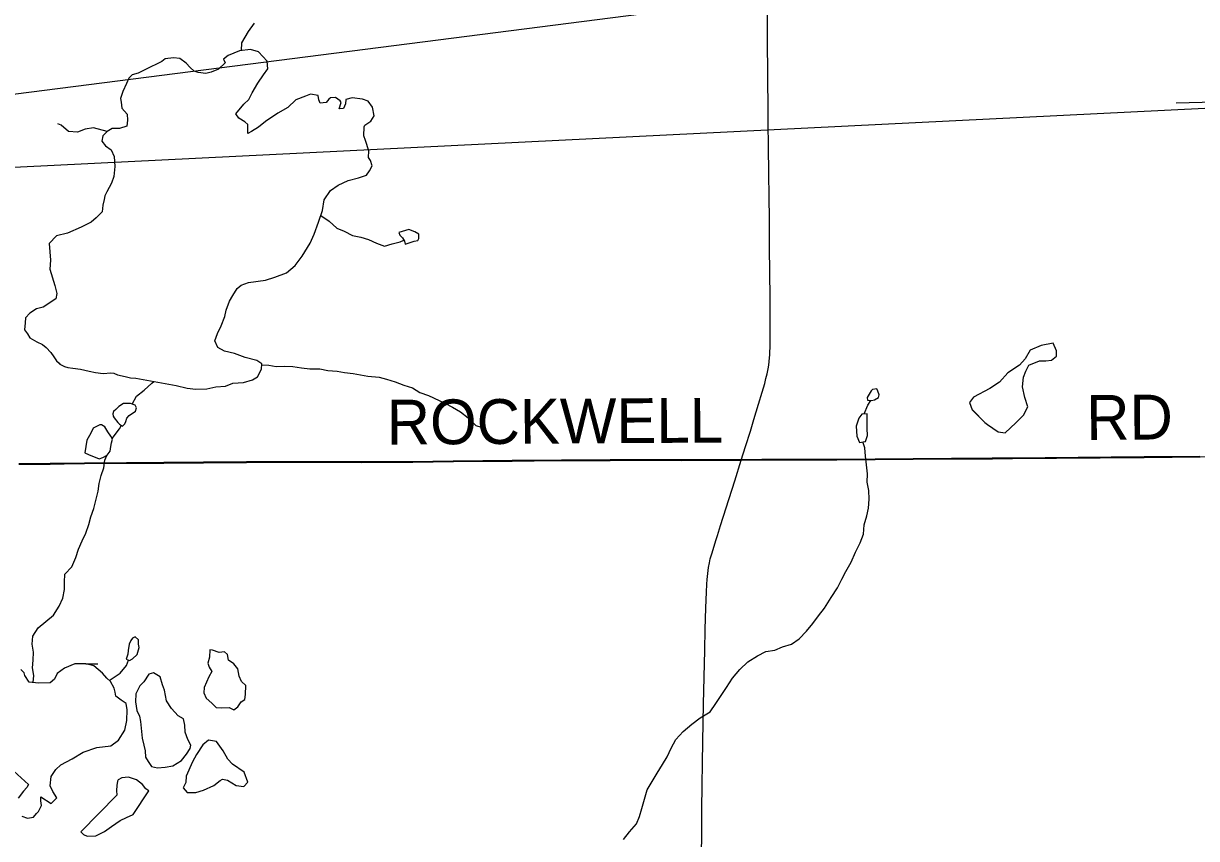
# Model space of a CAD drawing. Extents: x 0 to 34, y 0 to 22.
# Drawn here: x 6.114 to 7.601, y 17.032 to 18.065 of the extents above; entities that cross this region are included whole.
import ezdxf

# ---------------------------------------------------------------- set-up
doc = ezdxf.new("R2010")
doc.units = 0
for name, color, linetype in [('GM_X_Corporation', 7, 'Continuous'), ('GM_X_County_Road', 7, 'Continuous'), ('GM_X_County_Road_Text', 7, 'Continuous'), ('GM_X_Minor_Lake', 7, 'Continuous'), ('GM_X_Minor_River', 7, 'Continuous'), ('GM_X_Township_Road', 7, 'Continuous'), ('SH_Text', 7, 'Continuous')]:
    doc.layers.add(name, color=color, linetype=linetype)

msp = doc.modelspace()

# ---------------------------------------------------------------- linework, layer by layer
at = {"layer": 'GM_X_Corporation'}
for points in [[(7.6058, 17.5164), (7.5349, 17.5157), (7.3678, 17.5141), (7.3423, 17.514), (7.2907, 17.5138), (7.1453, 17.5127), (7.1242, 17.5126), (7.0981, 17.5126), (7.0758, 17.5124), (7.0504, 17.5124), (7.0238, 17.5123), (6.9875, 17.512), (6.9483, 17.512), (6.9334, 17.5121), (6.8907, 17.5122), (6.8578, 17.512), (6.7963, 17.5117), (6.7615, 17.5114), (6.7336, 17.5112), (6.659, 17.5104), (6.6074, 17.5097), (6.5789, 17.5096), (6.5428, 17.5095), (6.5174, 17.5095), (6.4677, 17.5096), (6.4548, 17.5095), (6.4362, 17.5096), (6.3967, 17.5095), (6.3422, 17.509), (6.3074, 17.5087), (6.2919, 17.5085), (6.2627, 17.5083), (6.2447, 17.5083), (6.1912, 17.5079), (6.1652, 17.5075), (6.1478, 17.5073), (6.108, 17.507)], [(6.108, 17.507), (6.1478, 17.5073), (6.1652, 17.5075), (6.1912, 17.5079), (6.2447, 17.5083), (6.2627, 17.5083), (6.2919, 17.5085), (6.3074, 17.5087), (6.3422, 17.509), (6.3967, 17.5095), (6.4362, 17.5096), (6.4548, 17.5095), (6.4677, 17.5096), (6.5174, 17.5095), (6.5428, 17.5095), (6.5789, 17.5096), (6.6074, 17.5097), (6.659, 17.5104), (6.7336, 17.5112), (6.7615, 17.5114), (6.7963, 17.5117), (6.8578, 17.512), (6.8907, 17.5122), (6.9334, 17.5121), (6.9483, 17.512), (6.9875, 17.512), (7.0238, 17.5123), (7.0504, 17.5124), (7.0758, 17.5124), (7.0981, 17.5126), (7.1242, 17.5126), (7.1453, 17.5127), (7.2907, 17.5138), (7.3423, 17.514), (7.3678, 17.5141), (7.5349, 17.5157), (7.6058, 17.5164)]]:
    msp.add_lwpolyline(points, dxfattribs=at)
at = {"layer": 'GM_X_County_Road'}
for points in [[(7.024, 17.5117), (7.0296, 17.5289), (7.0357, 17.5485), (7.0402, 17.5631), (7.0462, 17.5825), (7.0507, 17.5977), (7.0539, 17.6089), (7.0555, 17.615), (7.057, 17.6212), (7.0583, 17.6274), (7.059, 17.632), (7.0596, 17.6366), (7.06, 17.6413), (7.0602, 17.6451), (7.0607, 17.6584), (7.0608, 17.6656), (7.0608, 17.6743), (7.0608, 17.6897), (7.0608, 17.7179), (7.06, 17.7812), (7.0598, 17.8195), (7.0595, 17.8435), (7.059, 17.8774), (7.0587, 17.9072), (7.0586, 17.9179), (7.0584, 17.9305), (7.0582, 17.9612), (7.0579, 17.9922), (7.0574, 18.0516), (7.0572, 18.0766)], [(6.1082, 17.5065), (6.148, 17.5068), (6.1654, 17.507), (6.1914, 17.5074), (6.2449, 17.5077), (6.2629, 17.5078), (6.2921, 17.508), (6.3076, 17.5081), (6.3424, 17.5084), (6.3969, 17.5089), (6.4364, 17.509), (6.455, 17.509), (6.4679, 17.509), (6.5176, 17.509), (6.543, 17.5089), (6.5791, 17.509), (6.6077, 17.5091), (6.6592, 17.5098), (6.7338, 17.5106), (6.7617, 17.5108), (6.7965, 17.5111), (6.858, 17.5114), (6.8909, 17.5116), (6.9336, 17.5115), (6.9485, 17.5114), (6.9877, 17.5115), (7.024, 17.5117)], [(6.9738, 17.0165), (6.974, 17.0327), (6.974, 17.0507), (6.9741, 17.0618), (6.9742, 17.0699), (6.9745, 17.0984), (6.975, 17.1289), (6.976, 17.1792), (6.9764, 17.2024), (6.9779, 17.2709), (6.9784, 17.297), (6.9792, 17.3243), (6.9799, 17.3443), (6.9804, 17.3546), (6.9809, 17.3604), (6.9817, 17.3681), (6.9826, 17.3758), (6.9837, 17.3814), (6.9849, 17.3866), (6.9871, 17.3943), (6.9917, 17.4098), (6.9938, 17.4163), (6.9977, 17.4287), (7.005, 17.4511), (7.016, 17.4854), (7.024, 17.5117)], [(7.024, 17.5117), (7.0506, 17.5119), (7.076, 17.5119), (7.0983, 17.512), (7.1244, 17.512), (7.1455, 17.5122), (7.2909, 17.5132), (7.3425, 17.5134), (7.368, 17.5136), (7.5351, 17.5151), (7.606, 17.5158), (7.6644, 17.5163), (7.8224, 17.5169)]]:
    msp.add_lwpolyline(points, dxfattribs=at)
at = {"layer": 'GM_X_Minor_Lake'}
for p, q in [((6.5981, 17.7856), (6.6095, 17.7895)), ((6.2566, 17.6157), (6.3077, 17.6062)), ((7.1889, 17.5997), (7.1836, 17.5913)), ((7.317, 17.5753), (7.333, 17.5595)), ((7.333, 17.5595), (7.3178, 17.5749)), ((6.229, 17.5654), (6.2336, 17.5596)), ((7.1699, 17.5548), (7.1706, 17.5423)), ((6.1964, 17.5189), (6.2101, 17.5133)), ((6.2478, 17.2785), (6.2468, 17.2702)), ((6.3492, 17.2368), (6.3429, 17.2235)), ((6.2622, 17.1804), (6.2647, 17.1592)), ((6.1612, 17.1254), (6.1756, 17.1331)), ((6.3285, 17.1293), (6.3203, 17.1111)), ((6.253, 17.0624), (6.2728, 17.0925))]:
    msp.add_line(p, q, dxfattribs=at)
for points in [[(6.3077, 17.6062), (6.3214, 17.6029), (6.3324, 17.6015), (6.3464, 17.602), (6.3577, 17.6047), (6.3702, 17.6056), (6.3796, 17.6095), (6.3929, 17.6103), (6.4042, 17.6134), (6.4106, 17.6173), (6.4158, 17.6272), (6.4161, 17.634), (6.4097, 17.6381), (6.3953, 17.6418), (6.3816, 17.647), (6.3687, 17.6499), (6.3603, 17.6544), (6.3565, 17.6628), (6.3598, 17.6723), (6.3647, 17.6818), (6.3691, 17.6936), (6.3709, 17.7019), (6.3754, 17.7133), (6.3795, 17.7206), (6.3851, 17.7293), (6.39, 17.7335), (6.3994, 17.737), (6.421, 17.7399), (6.4327, 17.7437), (6.4474, 17.7492), (6.4583, 17.7583), (6.4673, 17.7705), (6.4774, 17.7866), (6.4826, 17.7983), (6.4882, 17.8132), (6.4933, 17.828), (6.4951, 17.8417), (6.5034, 17.8535), (6.5132, 17.8604), (6.5256, 17.8662), (6.5388, 17.8697), (6.549, 17.8732), (6.5528, 17.8785), (6.5561, 17.885), (6.5542, 17.8914), (6.5515, 17.8952), (6.5518, 17.9039), (6.5475, 17.9168), (6.5456, 17.9228), (6.5459, 17.9342), (6.547, 17.9365), (6.5545, 17.9415), (6.5586, 17.9484), (6.5567, 17.959), (6.5509, 17.9669), (6.5437, 17.9695), (6.5308, 17.9709), (6.5229, 17.9689), (6.5222, 17.9636), (6.5196, 17.9575), (6.5143, 17.9571), (6.5169, 17.9651), (6.5157, 17.9674), (6.5096, 17.9715), (6.5032, 17.9711), (6.501, 17.9692), (6.4976, 17.965), (6.49, 17.9641), (6.4885, 17.9683), (6.4877, 17.974), (6.4778, 17.9758), (6.4718, 17.9731), (6.4593, 17.9685), (6.4492, 17.9589), (6.4364, 17.9516), (6.4209, 17.9409), (6.4119, 17.934), (6.4032, 17.9282), (6.3983, 17.9259), (6.3986, 17.9373), (6.3948, 17.9407), (6.3872, 17.9452), (6.3834, 17.9508), (6.3935, 17.963), (6.3999, 17.9688), (6.404, 17.9775), (6.4111, 17.9897), (6.4182, 18), (6.4238, 18.008), (6.423, 18.0175), (6.4119, 18.0295), (6.4017, 18.0325), (6.3877, 18.0305), (6.3734, 18.0247), (6.3677, 18.0201), (6.3696, 18.0152), (6.3614, 18.0072), (6.3519, 18.0037), (6.3452, 18.0017), (6.3353, 18.0032), (6.3304, 18.005)], [(6.3304, 18.005), (6.3254, 18.0095), (6.3201, 18.0148), (6.3121, 18.0208), (6.3041, 18.0219), (6.2935, 18.0203), (6.2894, 18.0172), (6.2826, 18.0138), (6.2754, 18.0103), (6.2596, 18.0022), (6.2517, 18.0003), (6.2475, 17.996), (6.2446, 17.9892), (6.2401, 17.9789), (6.2372, 17.9702), (6.2379, 17.9656), (6.2388, 17.9581), (6.2453, 17.9505), (6.2461, 17.9426), (6.245, 17.9353), (6.2359, 17.9322), (6.2265, 17.9322), (6.2201, 17.9283), (6.2148, 17.923), (6.2133, 17.9161), (6.2179, 17.9101), (6.2252, 17.9052), (6.229, 17.8965), (6.2299, 17.884), (6.2285, 17.8711), (6.2255, 17.8628), (6.2195, 17.8517), (6.2173, 17.8468), (6.2162, 17.8422), (6.2147, 17.835), (6.2137, 17.8266), (6.2062, 17.819), (6.1998, 17.8136), (6.1873, 17.8071), (6.17, 17.7994), (6.156, 17.7962), (6.1466, 17.7863), (6.1483, 17.7651), (6.1476, 17.7537), (6.1538, 17.7333), (6.1562, 17.723), (6.1551, 17.7162), (6.1389, 17.7055), (6.1306, 17.7035), (6.1219, 17.6981), (6.1167, 17.692), (6.116, 17.6859), (6.1153, 17.6768), (6.1191, 17.6719), (6.1222, 17.6666), (6.1309, 17.6618), (6.1381, 17.6584), (6.1427, 17.6543), (6.1488, 17.6483), (6.1526, 17.6426), (6.1557, 17.6377), (6.1591, 17.6347), (6.1599, 17.6332), (6.166, 17.6306), (6.1702, 17.6291), (6.1766, 17.6284), (6.1861, 17.6269), (6.1974, 17.6247), (6.2054, 17.6229), (6.2149, 17.6215), (6.2247, 17.6223), (6.2285, 17.622), (6.2334, 17.6197), (6.2429, 17.6179), (6.2497, 17.616), (6.2566, 17.6157)], [(6.6095, 17.7895), (6.614, 17.7902), (6.6155, 17.7925), (6.6154, 17.7982), (6.6101, 17.8012), (6.6025, 17.8042), (6.5901, 17.8003), (6.5912, 17.7969), (6.5947, 17.7935), (6.597, 17.7894), (6.5981, 17.7856)], [(7.4197, 17.6599), (7.4042, 17.6571), (7.3906, 17.6513), (7.3842, 17.6402), (7.3771, 17.6319), (7.362, 17.6226), (7.3515, 17.6104), (7.3395, 17.6024), (7.3188, 17.5916), (7.3135, 17.5847), (7.317, 17.5753)], [(7.333, 17.5595), (7.3364, 17.5568), (7.3497, 17.5478), (7.3588, 17.5464), (7.3724, 17.559), (7.3821, 17.5689), (7.3874, 17.5792), (7.3839, 17.5913), (7.3807, 17.6046), (7.3818, 17.6167), (7.3851, 17.6243), (7.3888, 17.6319), (7.4024, 17.6377), (7.4104, 17.6378), (7.4175, 17.6386), (7.4239, 17.6436), (7.4239, 17.6504), (7.4197, 17.6599), (7.4042, 17.6571), (7.3906, 17.6513), (7.3842, 17.6402), (7.3771, 17.6319), (7.362, 17.6226), (7.3515, 17.6104), (7.3395, 17.6024), (7.3188, 17.5916), (7.3135, 17.5847), (7.317, 17.5753)], [(7.333, 17.5595), (7.3364, 17.5568), (7.3497, 17.5478), (7.3588, 17.5464), (7.3724, 17.559), (7.3821, 17.5689), (7.3874, 17.5792), (7.3839, 17.5913), (7.3807, 17.6046), (7.3818, 17.6167), (7.3851, 17.6243), (7.3888, 17.6319), (7.4024, 17.6377), (7.4104, 17.6378), (7.4175, 17.6386), (7.4239, 17.6436), (7.4239, 17.6504), (7.4197, 17.6599)], [(7.1836, 17.5913), (7.184, 17.5879), (7.1893, 17.5872), (7.1931, 17.588), (7.198, 17.591), (7.1988, 17.5945), (7.1972, 17.599), (7.196, 17.602), (7.1904, 17.6012), (7.1889, 17.5997)], [(6.2336, 17.5596), (6.2358, 17.5575), (6.2396, 17.5549), (6.2423, 17.5576), (6.2437, 17.5606), (6.2452, 17.5648), (6.2478, 17.5682), (6.2561, 17.5736), (6.2572, 17.5782), (6.2557, 17.5812), (6.2496, 17.5834), (6.2409, 17.5834), (6.2349, 17.5795), (6.2311, 17.5757), (6.2281, 17.5734), (6.2274, 17.5704), (6.2278, 17.5673), (6.229, 17.5654)], [(7.1706, 17.5423), (7.1739, 17.534), (7.1818, 17.5355), (7.184, 17.5428), (7.1836, 17.5519), (7.1839, 17.5606), (7.1838, 17.5705), (7.177, 17.57), (7.1732, 17.5651), (7.1699, 17.5548)], [(6.2101, 17.5133), (6.2146, 17.5149), (6.2202, 17.518), (6.224, 17.5229), (6.2247, 17.529), (6.2258, 17.5336), (6.2269, 17.5381), (6.2246, 17.5423), (6.2211, 17.5476), (6.2173, 17.554), (6.2131, 17.5566), (6.2108, 17.5566), (6.2022, 17.5524), (6.1996, 17.5459), (6.1943, 17.5371), (6.1918, 17.5208), (6.1964, 17.5189)], [(6.2468, 17.2702), (6.2464, 17.2656), (6.2442, 17.2595), (6.2484, 17.2577), (6.2522, 17.26), (6.2582, 17.2653), (6.2607, 17.2741), (6.26, 17.2782), (6.2599, 17.2839), (6.2557, 17.2877), (6.2523, 17.2858), (6.2501, 17.2831), (6.2478, 17.2785)], [(6.3429, 17.2235), (6.3426, 17.2167), (6.3456, 17.2099), (6.3529, 17.2035), (6.3582, 17.1982), (6.3647, 17.1975), (6.3749, 17.1983), (6.3806, 17.1953), (6.3859, 17.1988), (6.39, 17.2053), (6.3945, 17.2083), (6.3956, 17.2144), (6.3959, 17.2262), (6.3905, 17.2311), (6.3874, 17.2379), (6.3859, 17.247), (6.3809, 17.2534), (6.374, 17.2579), (6.3725, 17.2651), (6.369, 17.2688), (6.3622, 17.268), (6.3535, 17.2706), (6.3501, 17.271), (6.3498, 17.2619), (6.3479, 17.2543), (6.3495, 17.2493), (6.353, 17.2437), (6.3492, 17.2368)], [(6.1756, 17.1331), (6.1895, 17.1416), (6.2072, 17.1474), (6.2246, 17.1494), (6.2344, 17.1567), (6.2426, 17.1693), (6.2452, 17.1818), (6.2455, 17.1951), (6.2443, 17.203), (6.2378, 17.2075), (6.2313, 17.2124), (6.2302, 17.2177), (6.229, 17.2226), (6.2244, 17.2309), (6.2198, 17.2351), (6.2144, 17.2415), (6.2034, 17.2509), (6.1932, 17.2535), (6.1792, 17.2533), (6.166, 17.2479), (6.1565, 17.2414), (6.1532, 17.2342), (6.1479, 17.2292), (6.1332, 17.2291), (6.1214, 17.2301), (6.1157, 17.2388), (6.1149, 17.2422), (6.1107, 17.2464)], [(6.2647, 17.1592), (6.2666, 17.1505), (6.2682, 17.1433), (6.2687, 17.135), (6.2721, 17.1297), (6.2763, 17.1233), (6.2839, 17.1218), (6.2937, 17.1223), (6.3032, 17.1242), (6.3145, 17.1311), (6.3209, 17.1391), (6.3253, 17.146), (6.3261, 17.1502), (6.3226, 17.1577), (6.3191, 17.1668), (6.3187, 17.1755), (6.3171, 17.1839), (6.3102, 17.1876), (6.3018, 17.197), (6.2953, 17.2065), (6.2926, 17.2201), (6.2903, 17.2269), (6.2875, 17.2371), (6.2788, 17.242), (6.2731, 17.2404), (6.2668, 17.2305), (6.2615, 17.2255), (6.2563, 17.2153), (6.256, 17.2054), (6.2576, 17.1944), (6.2611, 17.1872), (6.2622, 17.1804)], [(6.3203, 17.1111), (6.32, 17.1031), (6.3166, 17.0963), (6.3216, 17.0902), (6.3326, 17.0903), (6.3424, 17.0931), (6.3552, 17.0992), (6.3635, 17.1057), (6.3665, 17.1073), (6.3726, 17.1058), (6.3836, 17.0991), (6.3935, 17.098), (6.3983, 17.1033), (6.3937, 17.1162), (6.3789, 17.1263), (6.3731, 17.1327), (6.367, 17.1433), (6.3586, 17.155), (6.3487, 17.1568), (6.3416, 17.1507), (6.3333, 17.1385), (6.3285, 17.1293)], [(6.1118, 17.0602), (6.119, 17.058), (6.1269, 17.0592), (6.1303, 17.0638), (6.1329, 17.0664), (6.137, 17.074), (6.1359, 17.0797), (6.1362, 17.0847), (6.1491, 17.0764), (6.1548, 17.0818), (6.1563, 17.0837), (6.1513, 17.0916), (6.1478, 17.0988), (6.1489, 17.1105), (6.1552, 17.1193), (6.1612, 17.1254)], [(6.1019, 17.1174), (6.1202, 17.1005), (6.1183, 17.0966), (6.1142, 17.0921), (6.1071, 17.0833)], [(6.2728, 17.0925), (6.269, 17.0951), (6.2648, 17.1004), (6.2575, 17.1064), (6.2473, 17.1098), (6.2386, 17.1089), (6.2341, 17.1066), (6.2333, 17.1047), (6.2322, 17.0994), (6.2319, 17.093), (6.2323, 17.0869), (6.1869, 17.0403), (6.1899, 17.0369), (6.1949, 17.035), (6.2059, 17.0355), (6.2168, 17.0409), (6.2254, 17.0474), (6.2367, 17.0547), (6.2447, 17.0586), (6.253, 17.0624)]]:
    msp.add_lwpolyline(points, dxfattribs=at)
at = {"layer": 'GM_X_Minor_River'}
for points in [[(6.3903, 18.0309), (6.391, 18.0408), (6.3992, 18.0552), (6.4071, 18.0655)], [(6.2201, 17.9283), (6.2026, 17.9331), (6.1924, 17.9312), (6.1826, 17.9277), (6.1712, 17.9283), (6.1617, 17.9362), (6.1575, 17.9381)], [(6.4912, 17.822), (6.5018, 17.8148), (6.5113, 17.8058), (6.5208, 17.8021), (6.5314, 17.7964), (6.5417, 17.7942), (6.5515, 17.7913), (6.5618, 17.7868), (6.5717, 17.7831), (6.5815, 17.7858), (6.5917, 17.7886), (6.5963, 17.7906)], [(6.4161, 17.6324), (6.4249, 17.6322), (6.4343, 17.6303), (6.4453, 17.6308), (6.4555, 17.6305), (6.4665, 17.6287), (6.4771, 17.6273), (6.4896, 17.6274), (6.4998, 17.6252), (6.5116, 17.6245), (6.5211, 17.6227), (6.532, 17.6216), (6.5506, 17.618), (6.565, 17.6169), (6.5745, 17.6144), (6.5851, 17.611), (6.5961, 17.6066), (6.6071, 17.6032), (6.6166, 17.5976), (6.6276, 17.5935), (6.6481, 17.5838), (6.658, 17.579), (6.6683, 17.573), (6.6778, 17.5655), (6.6877, 17.5557), (6.6942, 17.5534)], [(6.2517, 17.5826), (6.2571, 17.5926), (6.2669, 17.6006), (6.2767, 17.6094), (6.2792, 17.6115)], [(7.18, 17.5702), (7.1848, 17.5815), (7.1886, 17.5873)], [(6.2263, 17.5392), (6.2359, 17.5515), (6.2382, 17.5559)], [(6.9613, 17.177), (6.9722, 17.1851), (6.9846, 17.1928), (6.9918, 17.203), (6.9985, 17.2133), (7.0056, 17.2236), (7.0131, 17.2354), (7.0225, 17.2461), (7.0326, 17.2561), (7.0446, 17.2637), (7.0552, 17.2691), (7.0665, 17.2707), (7.0764, 17.275), (7.0877, 17.2785), (7.0975, 17.285), (7.1068, 17.2949), (7.1147, 17.3045), (7.1222, 17.3144), (7.1297, 17.3239), (7.1383, 17.3376), (7.1462, 17.3498), (7.1518, 17.3609), (7.1566, 17.3704), (7.1637, 17.3822), (7.1689, 17.3951), (7.1749, 17.4069), (7.1793, 17.418), (7.18, 17.4297), (7.1833, 17.4411), (7.1855, 17.451), (7.1865, 17.4624), (7.1861, 17.4734), (7.1837, 17.4836), (7.1844, 17.4942), (7.1828, 17.5056), (7.1816, 17.5166), (7.1807, 17.5272), (7.1781, 17.5348)], [(6.1264, 17.2297), (6.127, 17.2385), (6.1255, 17.2484), (6.1261, 17.2579), (6.1268, 17.2681), (6.1252, 17.2783), (6.1259, 17.2886), (6.1326, 17.2989), (6.1424, 17.3073), (6.1522, 17.3153), (6.1593, 17.3264), (6.1637, 17.3367), (6.1659, 17.3477), (6.1662, 17.3571), (6.1665, 17.367), (6.1752, 17.3766), (6.1804, 17.3884), (6.1837, 17.399), (6.1882, 17.4093), (6.193, 17.4192), (6.1967, 17.4302), (6.1996, 17.4397), (6.2034, 17.4503), (6.2085, 17.4724), (6.2099, 17.4819), (6.2125, 17.4921), (6.2158, 17.502), (6.2173, 17.5115), (6.2195, 17.5176)], [(6.2226, 17.2325), (6.2368, 17.2416), (6.2447, 17.2512), (6.2473, 17.2582)], [(6.1932, 17.2535), (6.2083, 17.2536)], [(6.8747, 17.0308), (6.8825, 17.0403), (6.8915, 17.0506), (6.8952, 17.0601), (6.8982, 17.07), (6.9015, 17.0818), (6.9048, 17.0939), (6.9112, 17.1042), (6.9175, 17.1149), (6.9242, 17.1259), (6.9302, 17.1355), (6.9351, 17.1465), (6.941, 17.1575), (6.9504, 17.1675), (6.9613, 17.177)]]:
    msp.add_lwpolyline(points, dxfattribs=at)
at = {"layer": 'GM_X_Township_Road'}
msp.add_lwpolyline([(7.5755, 17.9649), (7.7732, 17.9697), (7.8, 17.9706), (7.8908, 17.973), (7.9205, 17.9733)], dxfattribs=at)
at = {"layer": 'SH_Text'}
msp.add_lwpolyline([(9.3865, 18.3957), (4.9237, 17.8249), (9.3865, 18.0457)], close=True, dxfattribs=at)

# ---------------------------------------------------------------- texts
at = {"layer": 'GM_X_County_Road_Text'}
for s, rotation, p in [('ROCKWELL', 0.3709, (6.5748, 17.5313)), ('RD', 0.4827, (7.4618, 17.5372))]:
    msp.add_text(s, height=0.05682, rotation=rotation, dxfattribs=at).set_placement(p)

doc.saveas('drawing.dxf')
